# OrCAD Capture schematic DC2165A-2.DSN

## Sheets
1 PAGE4: size A
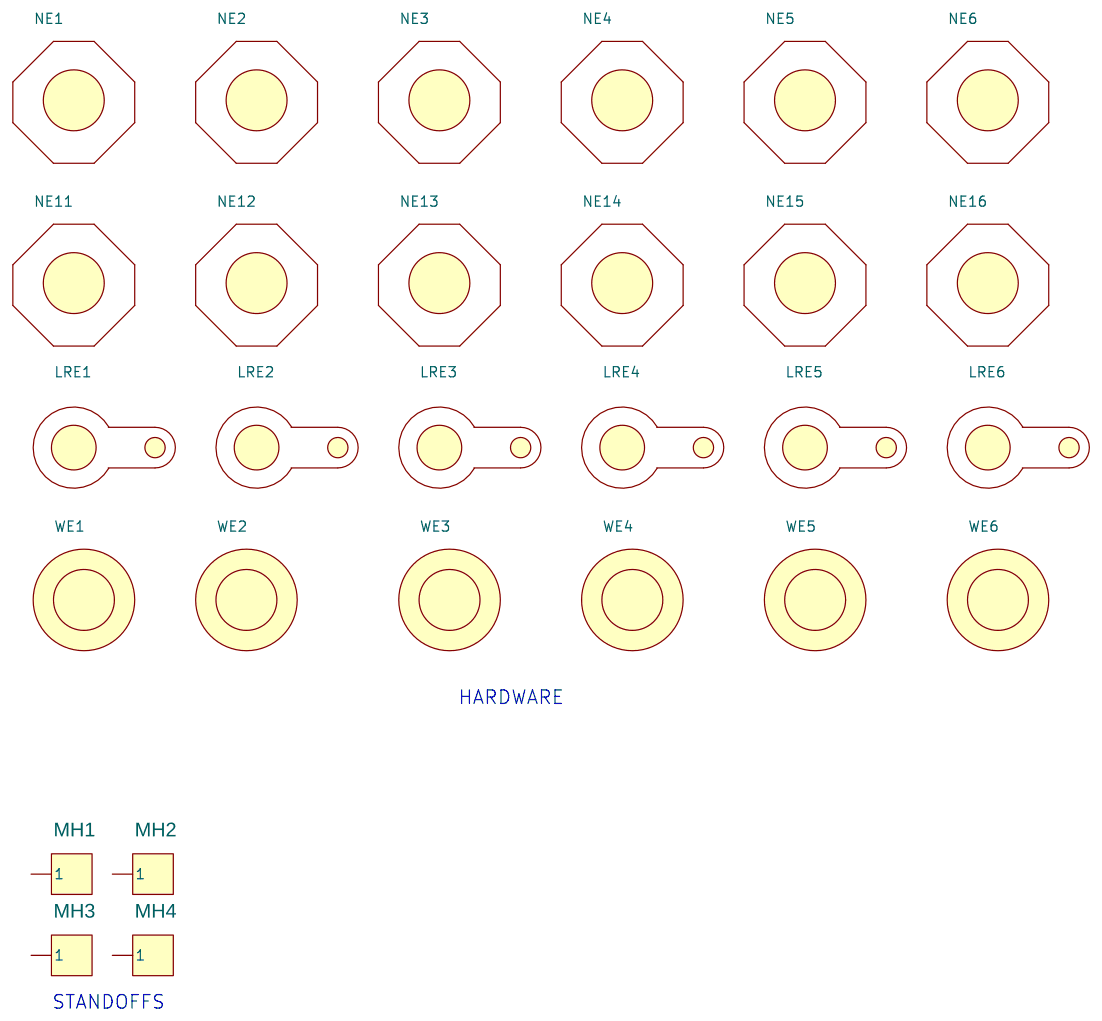
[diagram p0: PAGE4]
2 PAGE2: size Custom; title: HIGH EFFICIENCY, DUAL-OUTPUT SYNCHRONOUS BUCK; rev: 2; company: TM; note: CONVERTER WITH POWER SYSTEM MANAGEMENT
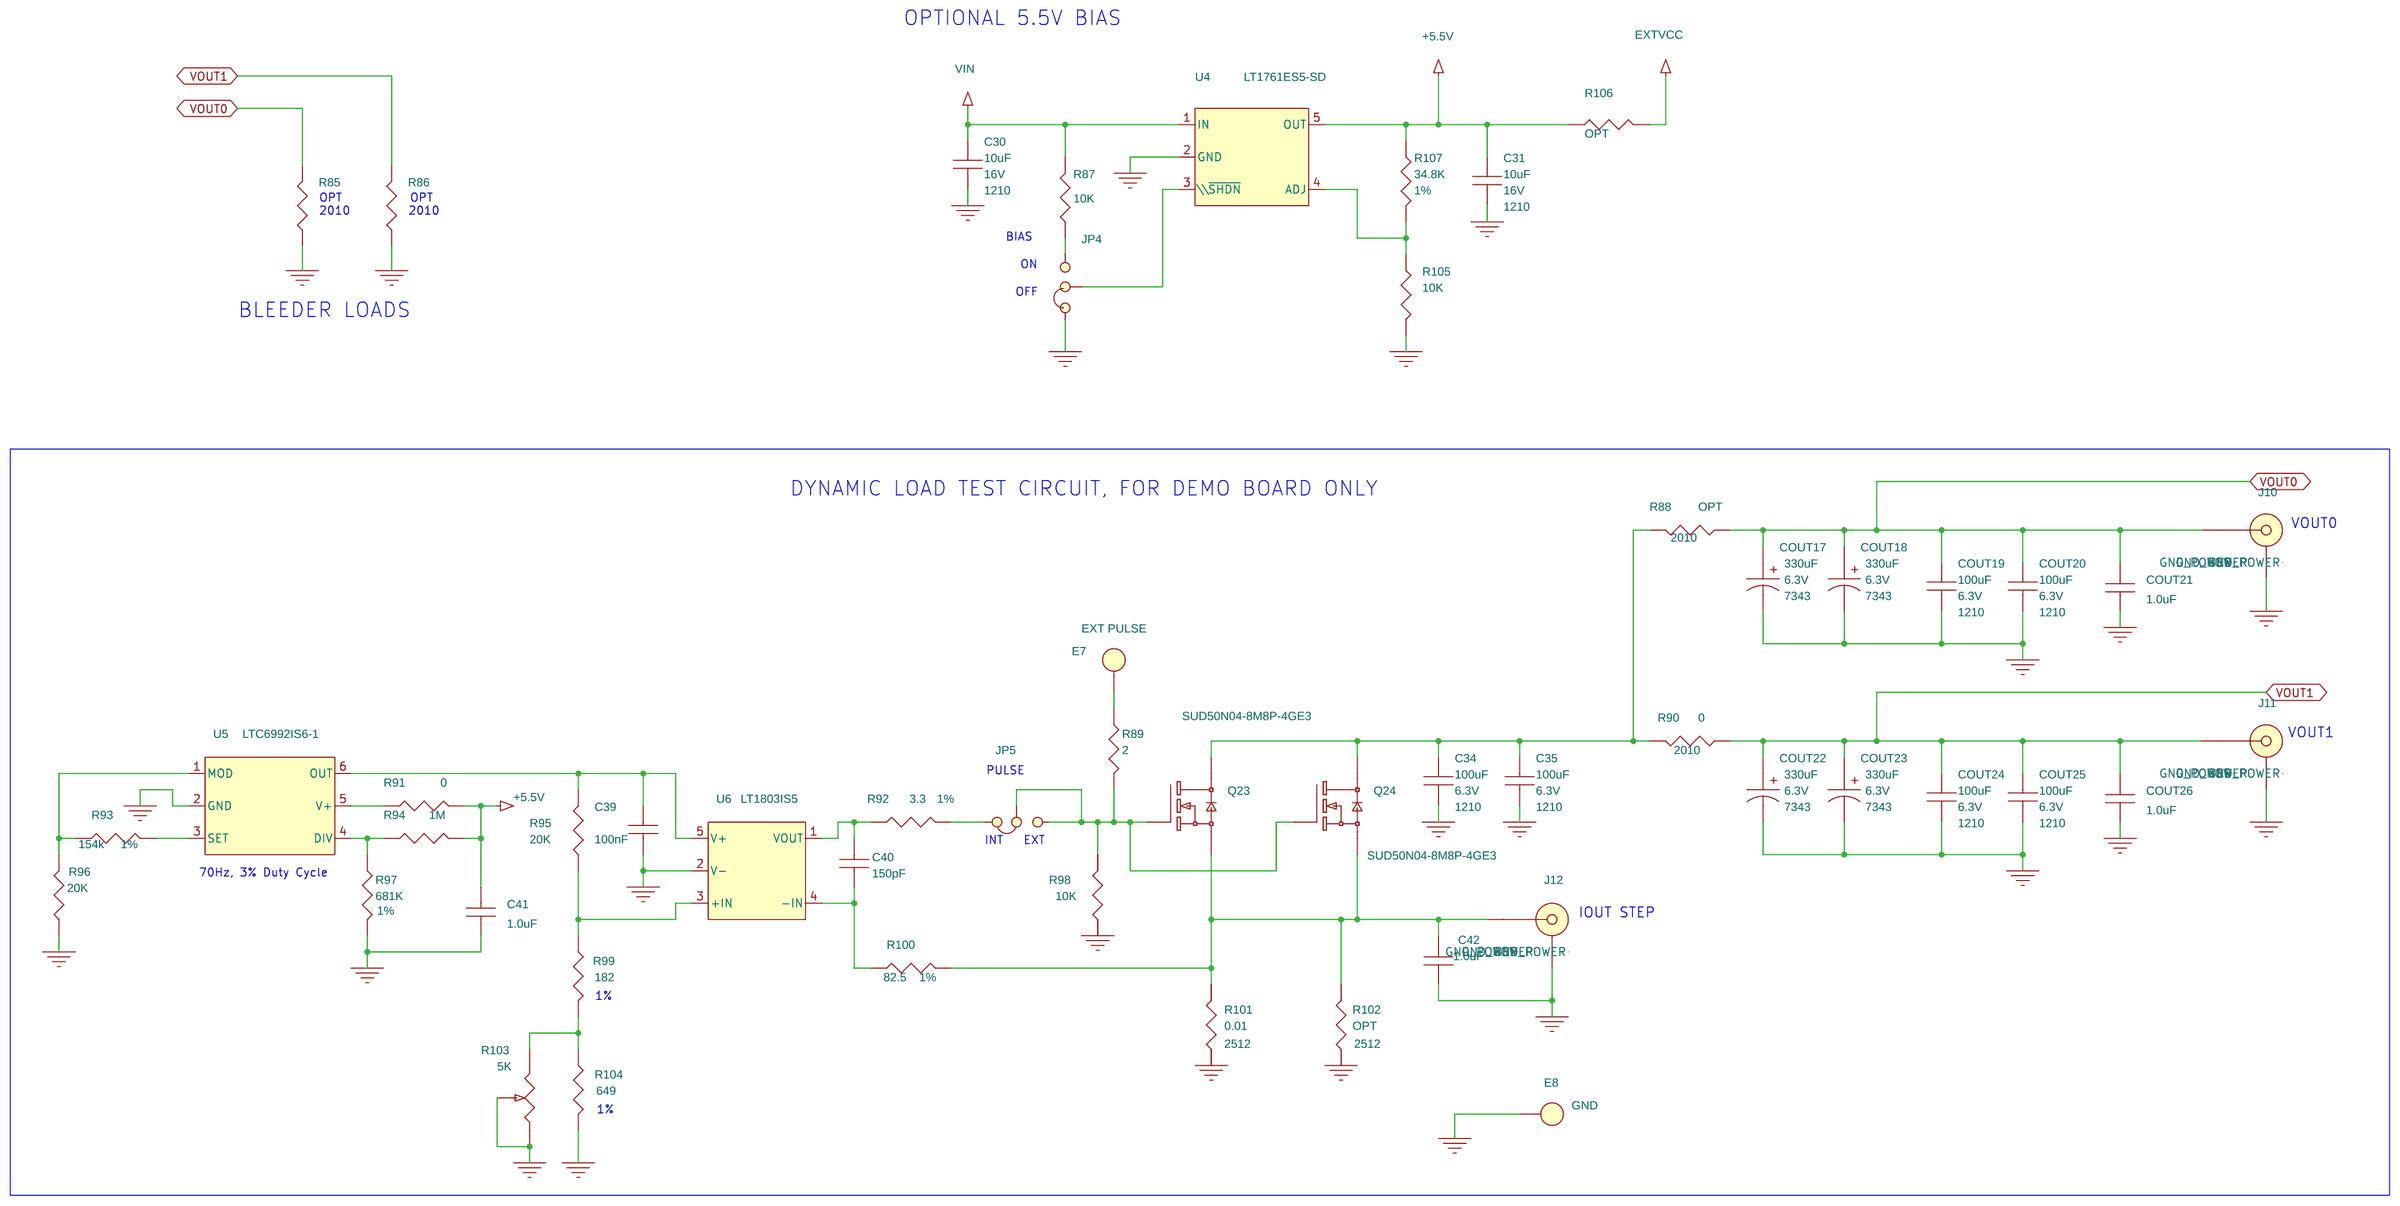
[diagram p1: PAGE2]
3 PAGE1: size Custom; title: HIGH EFFICIENCY, DUAL-OUTPUT SYNCHRONOUS BUCK; rev: 2; company: TM; note: CONVERTER WITH POWER SYSTEM MANAGEMENT
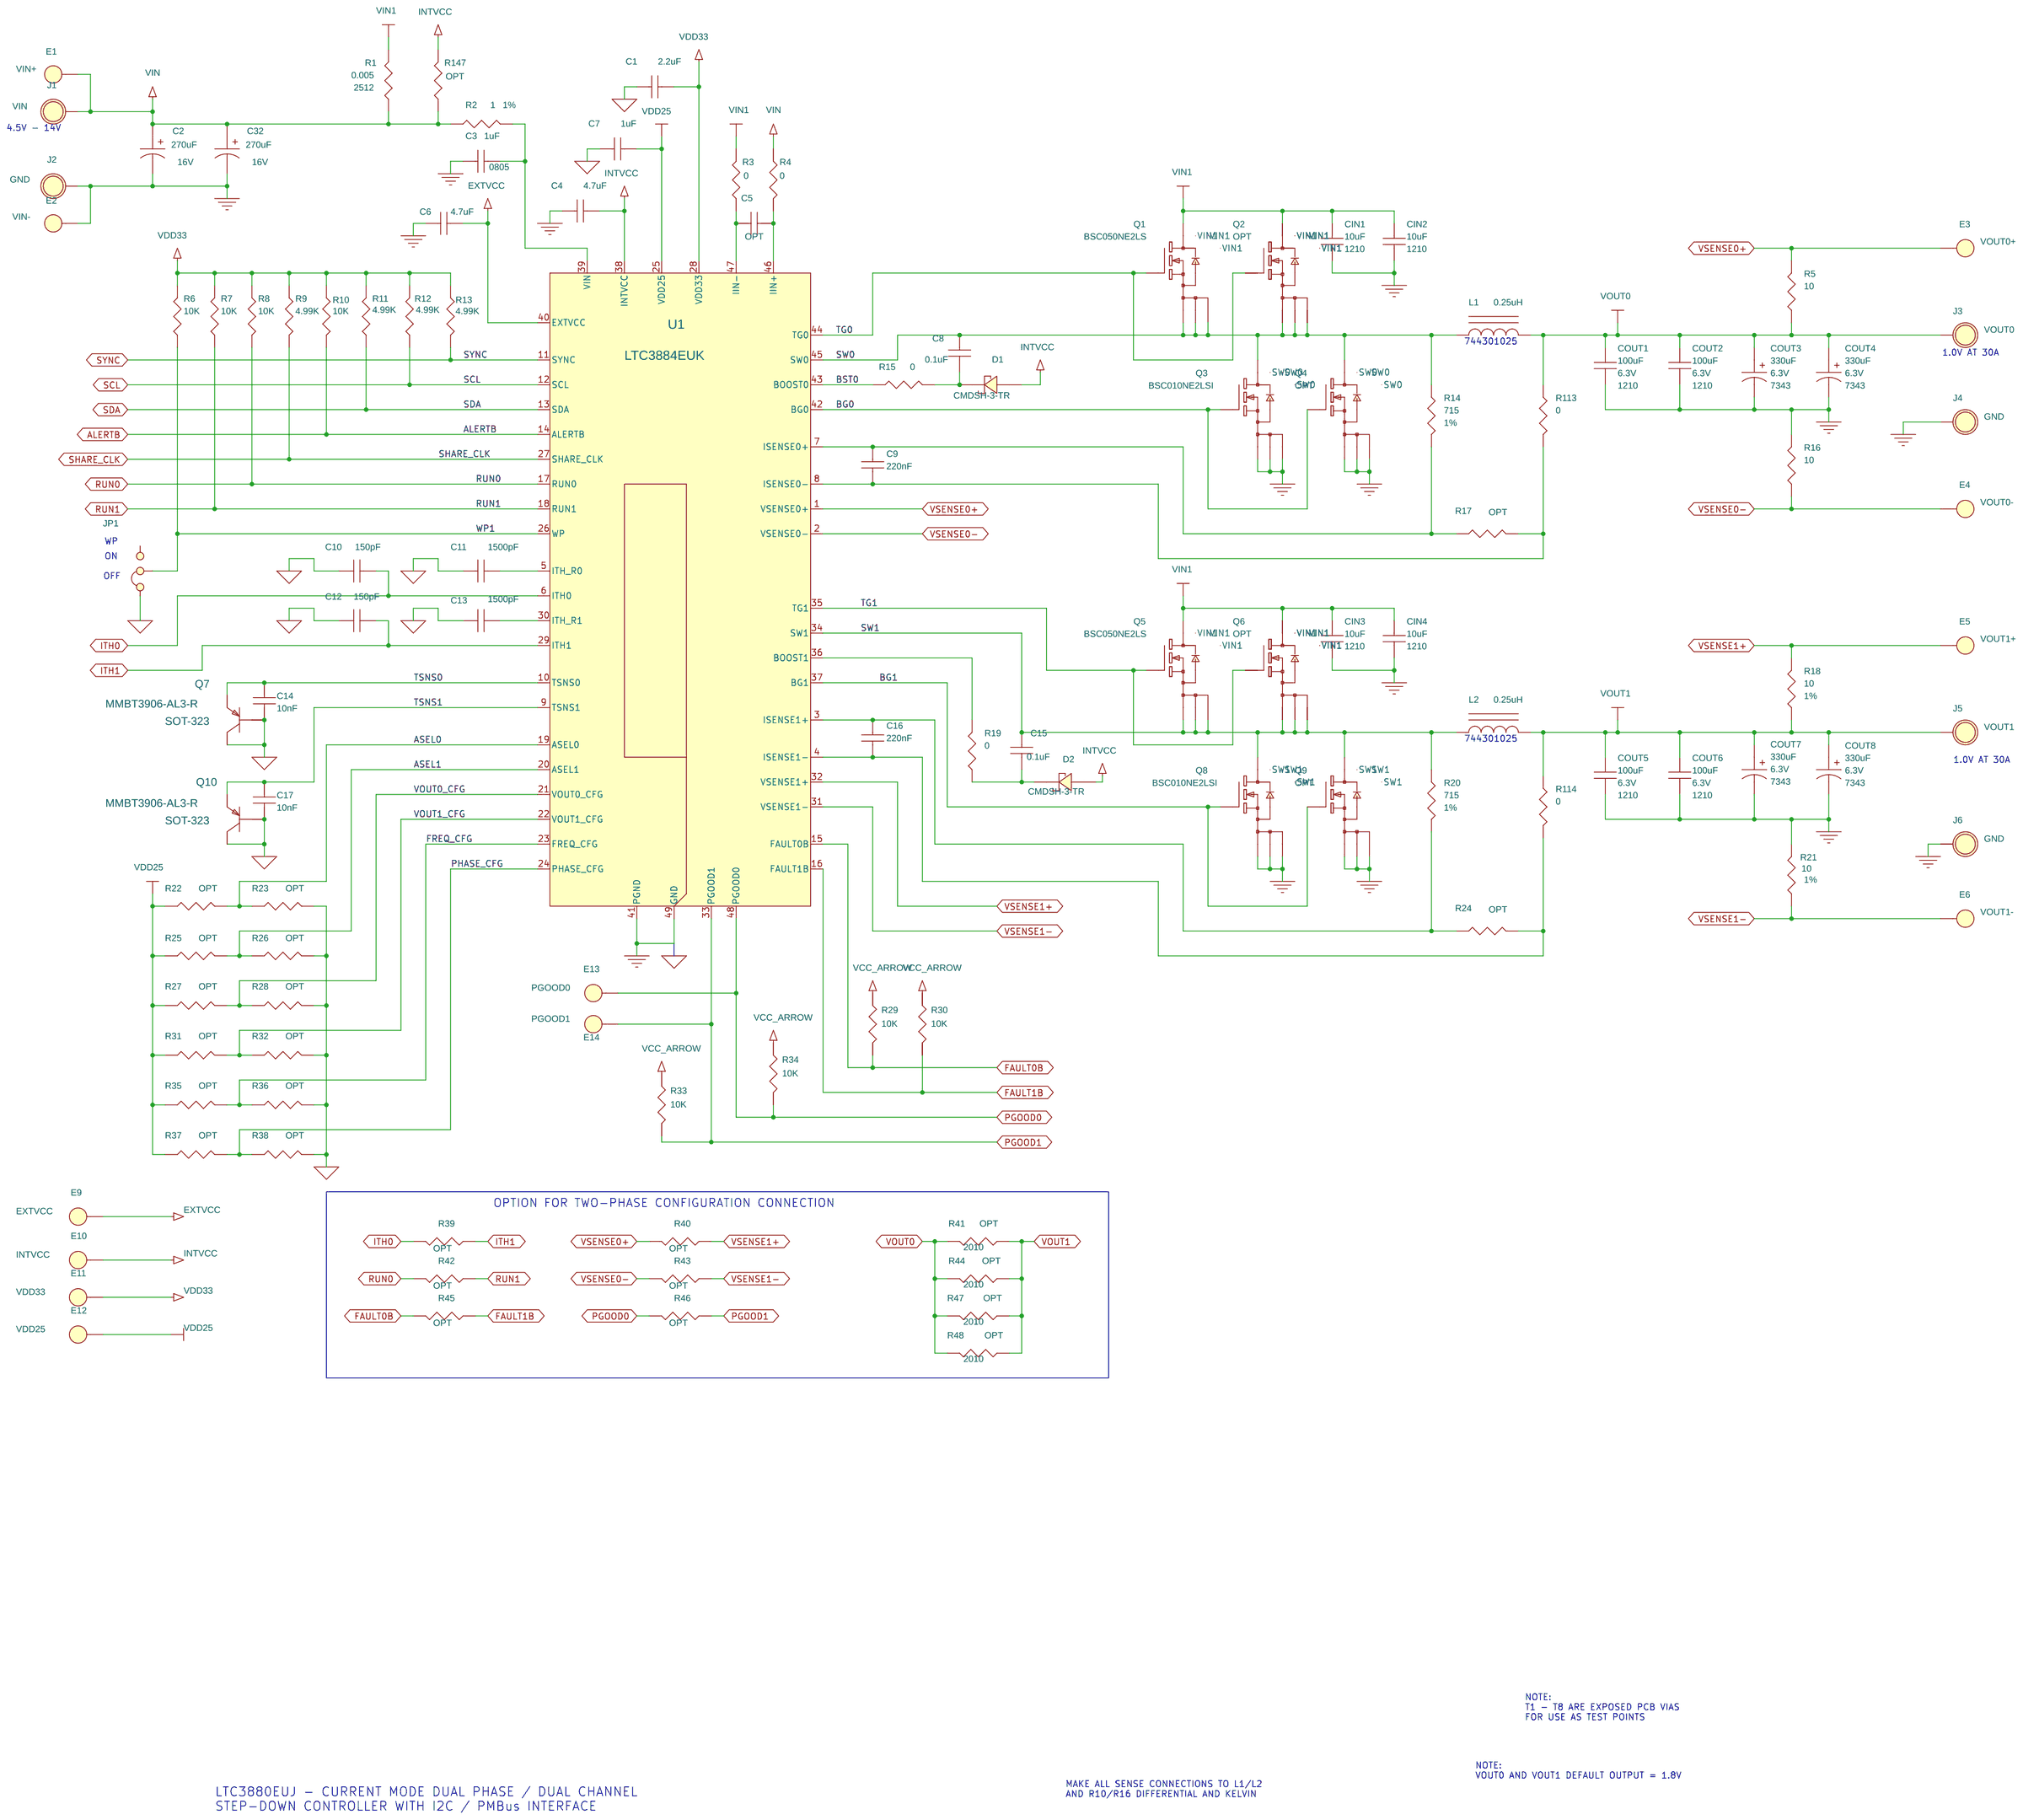
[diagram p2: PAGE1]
4 PAGE3: size Custom; title: HIGH EFFICIENCY, DUAL-OUTPUT SYNCHRONOUS BUCK; rev: 2; company: TM; note: CONVERTER WITH POWER SYSTEM MANAGEMENT
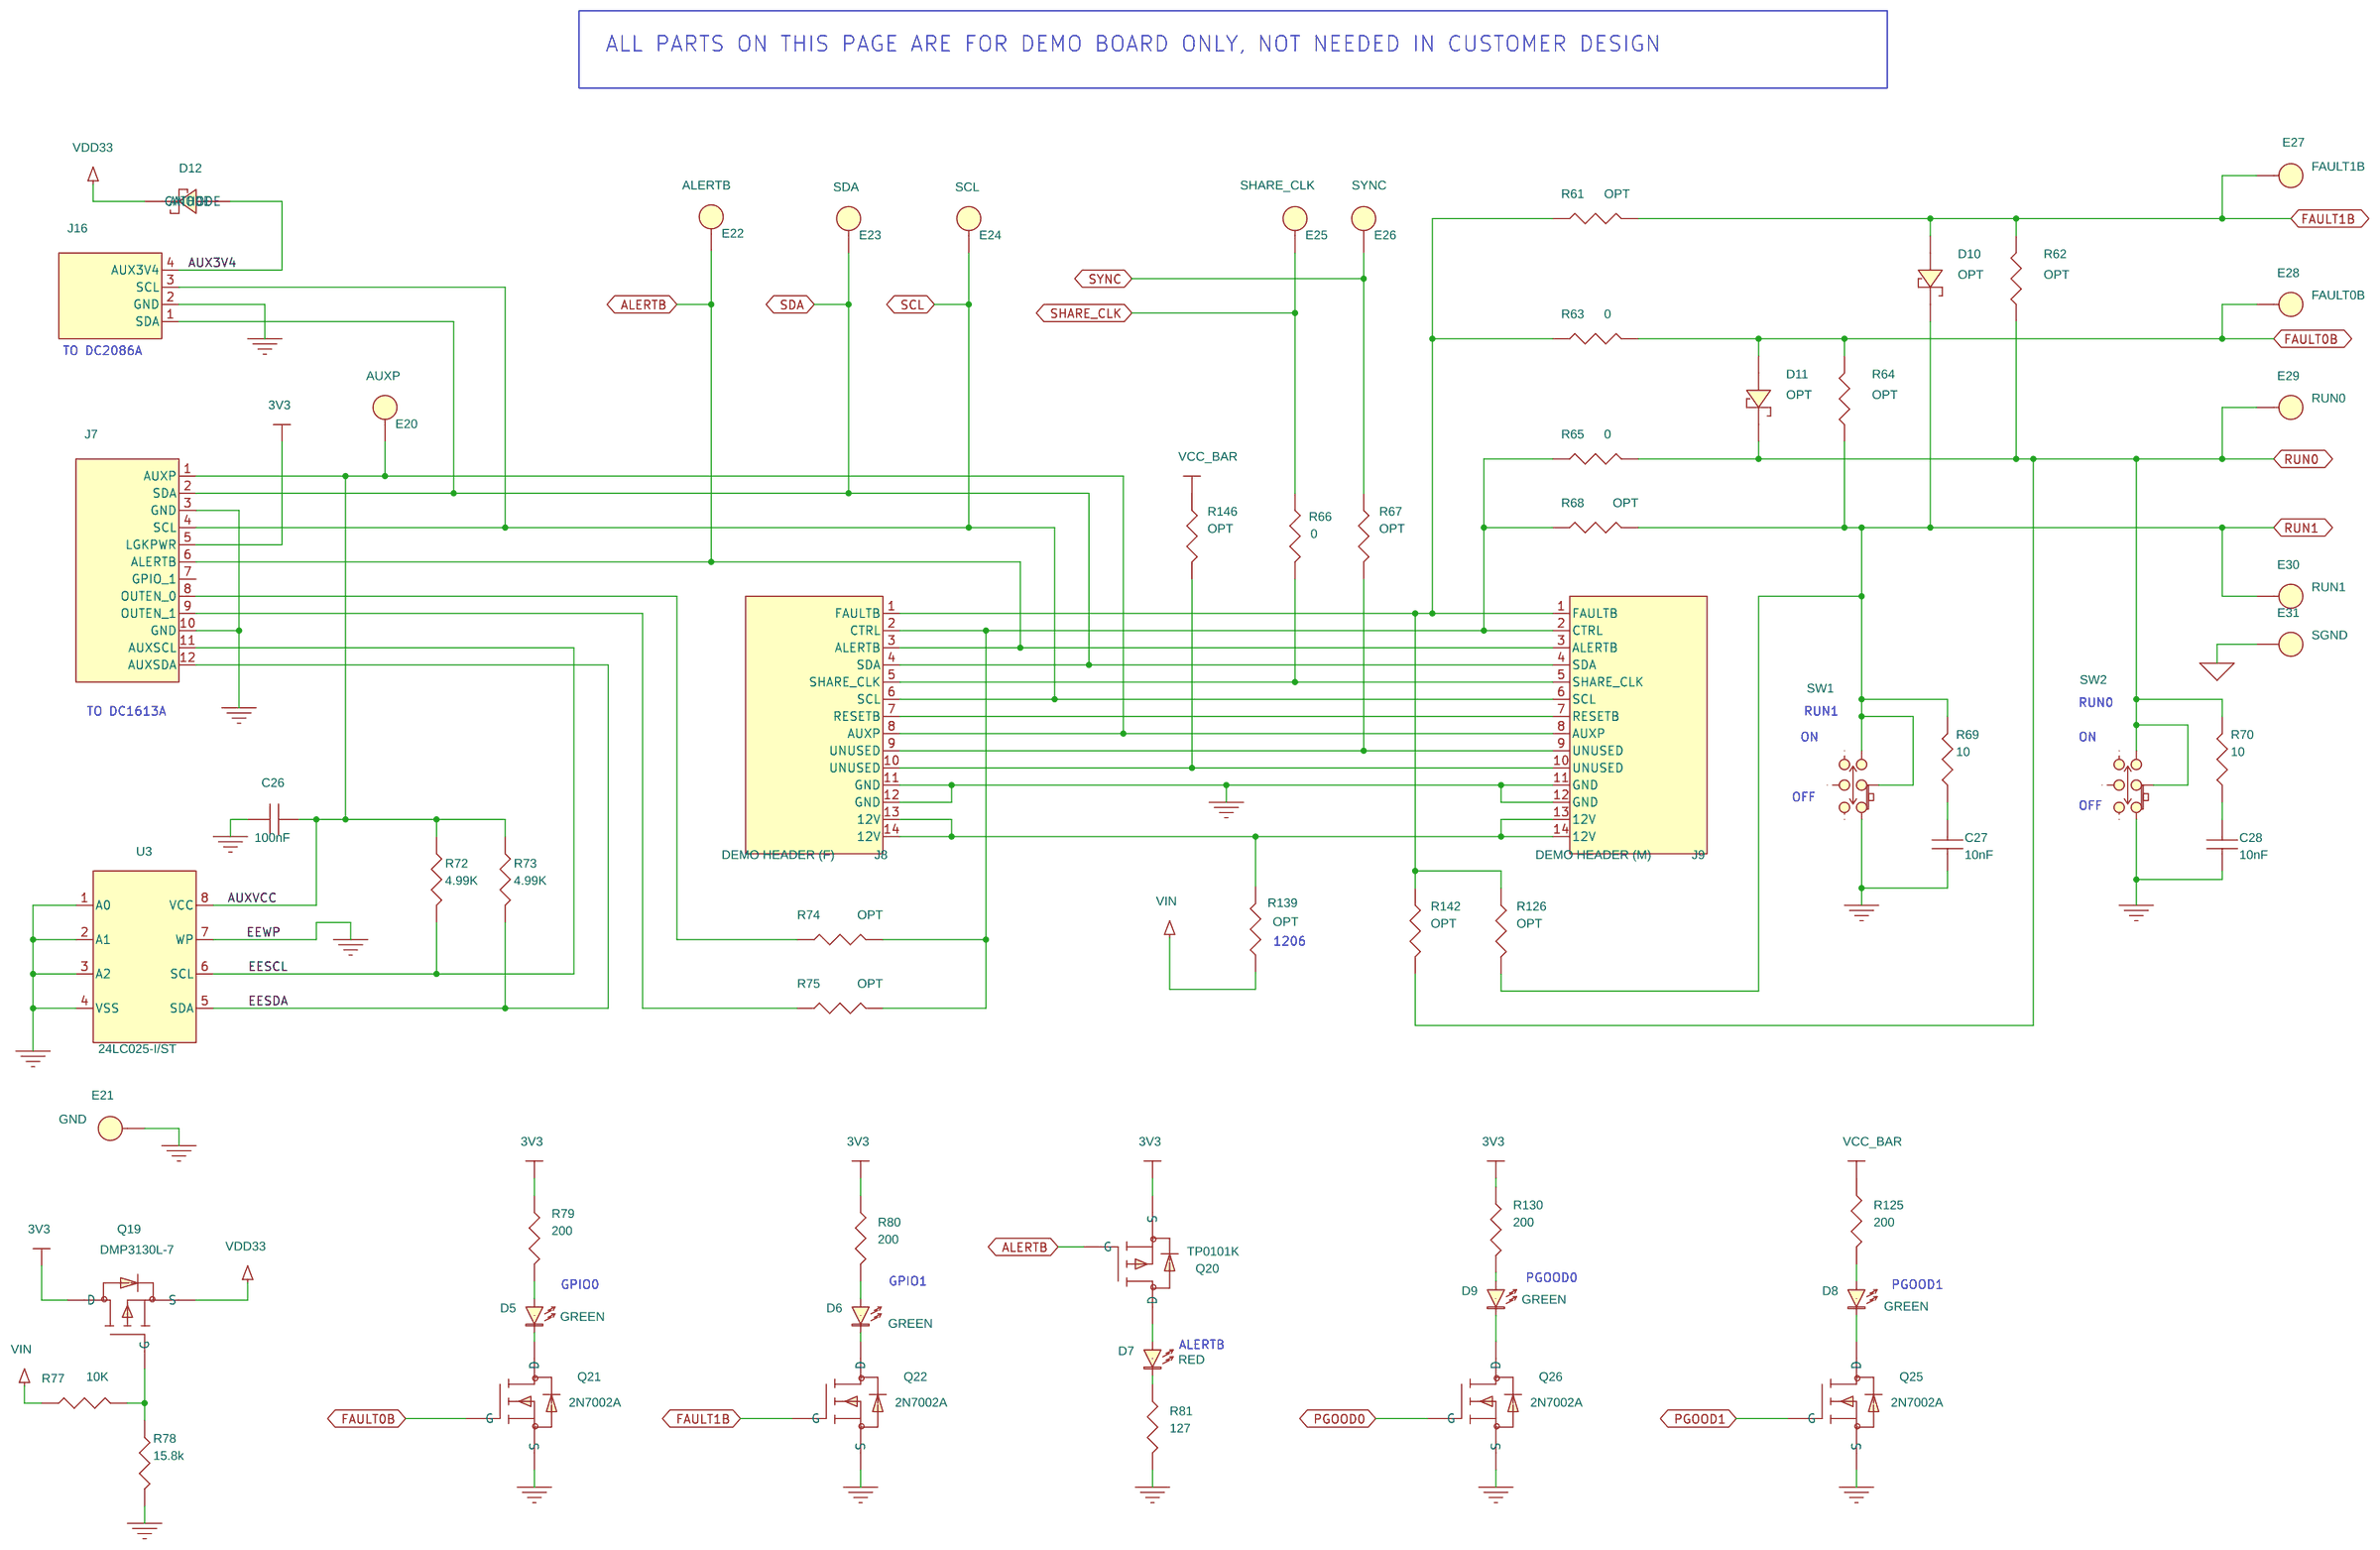
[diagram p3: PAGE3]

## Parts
sheet PAGE1
C1  2.2uF  [0603]
C2  270uF  [CAP\SAN\OSCON\SVF12]
C3  1uF  [0805]
C4  4.7uF  [0603]
C5  OPT  [0603]
C6  4.7uF  [0603]
C7  1uF  [0603]
C8  0.1uF  [0603]
C9  220nF  [0603]
C10  150pF  [0603]
C11  1500pF  [0603]
C12  150pF  [0603]
C13  1500pF  [0603]
C14  10nF  [0603]
C15  0.1uF  [0603]
C16  220nF  [0603]
C17  10nF  [0603]
C32  270uF  [CAP\SAN\OSCON\SVF12]
CIN1  10uF  [1210]
CIN2  10uF  [1210]
CIN3  10uF  [1210]
CIN4  10uF  [1210]
COUT1  100uF  [1210]
COUT2  100uF  [1210]
COUT3  330uF  [7343]
COUT4  330uF  [7343]
COUT5  100uF  [1210]
COUT6  100uF  [1210]
COUT7  330uF  [7343]
COUT8  330uF  [7343]
D1  CMDSH-3-TR  [SOD323]
D2  CMDSH-3-TR  [SOD323]
E1  VIN+  [TP\MMX\2501-2]
E2  VIN-  [TP\MMX\2501-2]
E3  VOUT0+  [TP\MMX\2501-2]
E4  VOUT0-  [TP\MMX\2501-2]
E5  VOUT1+  [TP\MMX\2501-2]
E6  VOUT1-  [TP\MMX\2501-2]
E9  EXTVCC  [TP\MMX\2501-2]
E10  INTVCC  [TP\MMX\2501-2]
E11  VDD33  [TP\MMX\2501-2]
E12  VDD25  [TP\MMX\2501-2]
E13  PGOOD0  [TP\MMX\2501-2]
E14  PGOOD1  [TP\MMX\2501-2]
J1  BANANA SMALL  [CON\LUG\10]
J2  BANANA SMALL  [CON\LUG\10]
J3  BANANA SMALL  [CON\LUG\10]
J4  BANANA SMALL  [CON\LUG\10]
J5  BANANA SMALL  [CON\LUG\10]
J6  BANANA SMALL  [CON\LUG\10]
JP1  JP3X1/079\NO\12  [SIP\3P\2MM]
L1  0.25uH  [IND\WURTH\7443010XX]
L2  0.25uH  [IND\WURTH\7443010XX]
Q1  BSC050NE2LS  [PWRPK_SO8]
Q2  OPT  [PWRPK_SO8]
Q3  BSC010NE2LSI  [PWRPK_SO8]
Q4  OPT  [PWRPK_SO8]
Q5  BSC050NE2LS  [PWRPK_SO8]
Q6  OPT  [PWRPK_SO8]
Q7  MMBT3906-AL3-R  [SOT-323]
Q8  BSC010NE2LSI  [PWRPK_SO8]
Q9  OPT  [PWRPK_SO8]
Q10  MMBT3906-AL3-R  [SOT-323]
R1  0.005  [2512]
R2  1  [0603]
R3  0  [0603]
R4  0  [0603]
R5  10  [0603]
R6  10K  [0603]
R7  10K  [0603]
R8  10K  [0603]
R9  4.99K  [0603]
R10  10K  [0603]
R11  4.99K  [0603]
R12  4.99K  [0603]
R13  4.99K  [0603]
R14  715  [0603]
R15  0  [0603]
R16  10  [0603]
R17  OPT  [0603]
R18  10  [0603]
R19  0  [0603]
R20  715  [0603]
R21  10  [0603]
R22  OPT  [0603]
R23  OPT  [0603]
R24  OPT  [0603]
R25  OPT  [0603]
R26  OPT  [0603]
R27  OPT  [0603]
R28  OPT  [0603]
R29  10K  [0603]
R30  10K  [0603]
R31  OPT  [0603]
R32  OPT  [0603]
R33  10K  [0603]
R34  10K  [0603]
R35  OPT  [0603]
R36  OPT  [0603]
R37  OPT  [0603]
R38  OPT  [0603]
R39  OPT  [0603]
R40  OPT  [0603]
R41  OPT  [2010]
R42  OPT  [0603]
R43  OPT  [0603]
R44  OPT  [2010]
R45  OPT  [0603]
R46  OPT  [0603]
R47  OPT  [2010]
R48  OPT  [2010]
R113  0  [0603]
R114  0  [0603]
R147  OPT  [0603]
U1  LTC3884EUK  [LT_UK48_7X7]
XJP1  SHUNT  [NONE]
sheet PAGE2
C30  10uF  [1210]
C31  10uF  [1210]
C34  100uF  [1210]
C35  100uF  [1210]
C39  100nF  [0603]
C40  150pF  [0603]
C41  1.0uF  [0603]
C42  1.0uF  [0603]
COUT17  330uF  [7343]
COUT18  330uF  [7343]
COUT19  100uF  [1210]
COUT20  100uF  [1210]
COUT21  1.0uF  [0603]
COUT22  330uF  [7343]
COUT23  330uF  [7343]
COUT24  100uF  [1210]
COUT25  100uF  [1210]
COUT26  1.0uF  [0603]
E7  EXT PULSE  [TP\MMX\2501-2]
E8  GND  [TP\MMX\2501-2]
J10  XXX  [BNC5]
J11  XXX  [BNC5]
J12  XXX  [BNC5]
JP4  JP3X1/079\NO\12  [SIP\3P\2MM]
JP5  JP3X1/079\NO\12  [SIP\3P\2MM]
Q23  SUD50N04-8M8P-4GE3  [TO-252]
Q24  SUD50N04-8M8P-4GE3  [TO-252]
R85  OPT  [2512]
R86  OPT  [2512]
R87  10K  [0603]
R88  OPT  [2010]
R89  2  [0603]
R90  0  [2010]
R91  0  [0603]
R92  3.3  [0603]
R93  154k  [0603]
R94  1M  [0603]
R95  20K  [0603]
R96  20K  [0603]
R97  681K  [0603]
R98  10K  [0603]
R99  182  [0603]
R100  82.5  [0603]
R101  0.01  [2512]
R102  OPT  [2512]
R103  5K  [BOURNS_3386P]
R104  649  [0603]
R105  10K  [0603]
R106  OPT  [0603]
R107  34.8K  [0603]
U4  LT1761ES5-SD  [LT_TSOT-23-S5]
U5  LTC6992IS6-1  [LT_S6]
U6  LT1803IS5  [LT_S5]
XJP4  SHUNT  [NONE]
XJP5  SHUNT  [NONE]
sheet PAGE3
C26  100nF  [0603]
C27  10nF  [0603]
C28  10nF  [0603]
D5  GREEN  [LED_0603]
D6  GREEN  [LED_0603]
D7  RED  [LED_0603]
D8  GREEN  [LED_0603]
D9  GREEN  [LED_0603]
D10  OPT  [SOD323]
D11  OPT  [SOD323]
D12  DIODE SCHOTTKY  [SOD882]
E20  AUXP  [TP\MMX\2501-2]
E21  GND  [TP\MMX\2501-2]
E22  ALERTB  [TP\MMX\2501-2]
E23  SDA  [TP\MMX\2501-2]
E24  SCL  [TP\MMX\2501-2]
E25  SHARE_CLK  [TP\MMX\2501-2]
E26  SYNC  [TP\MMX\2501-2]
E27  FAULT1B  [TP\MMX\2501-2]
E28  FAULT0B  [TP\MMX\2501-2]
E29  RUN0  [TP\MMX\2501-2]
E30  RUN1  [TP\MMX\2501-2]
E31  SGND  [TP\MMX\2501-2]
J7  HD2X6-079  [HD2X6-079-MOLEX]
J8  DEMO HEADER (F)  [NPPN072FJFN-RC]
J9  DEMO HEADER (M)  [NPPN072FJFN]
J16  HD2X6-079-PMBUS_0  [CON\HRS\DF3A-4P-2DSA]
Q19  DMP3130L-7  [SOT23]
Q20  TP0101K  [SOT23]
Q21  2N7002A  [SOT23]
Q22  2N7002A  [SOT23]
Q25  2N7002A  [SOT23]
Q26  2N7002A  [SOT23]
R61  OPT  [0603]
R62  OPT  [0603]
R63  0  [0603]
R64  OPT  [0603]
R65  0  [0603]
R66  0  [0603]
R67  OPT  [0603]
R68  OPT  [0603]
R69  10  [0603]
R70  10  [0603]
R72  4.99K  [0603]
R73  4.99K  [0603]
R74  OPT  [0603]
R75  OPT  [0603]
R77  10K  [0603]
R78  15.8k  [0603]
R79  200  [0603]
R80  200  [0603]
R81  127  [0603]
R125  200  [0603]
R126  OPT  [0603]
R130  200  [0603]
R139  OPT  [1206]
R142  OPT  [0603]
R146  OPT  [0603]
SW1  JP3X1/079\NO\12  [JS202011]
SW2  JP3X1/079\NO\12  [JS202011]
U3  24LC025-I/ST  [TSSOP-8_4.4MM]
sheet PAGE4
LRE1  Lug_Ring
LRE2  Lug_Ring
LRE3  Lug_Ring
LRE4  Lug_Ring
LRE5  Lug_Ring
LRE6  Lug_Ring
MH1  CON1  [KEYSTONE_8831]
MH2  CON1  [KEYSTONE_8831]
MH3  CON1  [KEYSTONE_8831]
MH4  CON1  [KEYSTONE_8831]
NE1  NUT
NE2  NUT
NE3  NUT
NE4  NUT
NE5  NUT
NE6  NUT
NE11  NUT
NE12  NUT
NE13  NUT
NE14  NUT
NE15  NUT
NE16  NUT
WE1  Washer
WE2  Washer
WE3  Washer
WE4  Washer
WE5  Washer
WE6  Washer

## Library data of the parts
C1 = CAP_NP: CAP, 0603 2.2uF 20% 6.3V X5R; Part Number: AVX 06036D225MAT2A; Volts/Amps/Watts: 50V
C2 C32 = CAPR12X5_0: CAP, 270uF 20% 16V OSCON; Component: cap; Manufacturer: SANYO; Part Number: PANASONIC 16SVPC270M; Tolerance: 20%; Type: OS-CON; Volts/Amps/Watts: 16V
C3 = CAP_NP_0: CAP, 0805 1uF 10% 16V X7R; Part Number: AVX 0805YC105KAT2A
C4 = CAP_NP: CAP, 0603 4.7uF 10% 10V X5R; Part Number: AVX 0603ZD475KAT2A
C5 = CAP_NP: CAP, 0603 OPTION; Part Number: OPTION
C6 = CAP_NP: CAP, 0603 4.7uF 20% 25V X5R; Part Number: TDK  C1608X5R1E475M080AC
C7 C41 COUT21 COUT26 = CAP_NP: CAP, 0603 1uF 20% 25V X5R; Part Number: AVX 06033D105MAT2A
C8 C15 = CAP_NP_0: CAP, 0603 0.1uF 10% 25V X7R; Part Number: AVX 06033C104KAT2A; VOLTAGE: 50V
C9 C16 = CAP_NP: CAP, 0603 220nF 10% 25V X7R; Part Number: TDK C1608X7R1E224K
C10 C12 C40 = CAP_NP: CAP, 0603 150pF 5% 50V NPO; Part Number: AVX 06035A151JAT2A
C11 C13 = CAP_NP: CAP, 0603 1500pF 5% 50V C0G; Part Number: MURATA GRM1885C1H152JA01D
C14 C17 C27 C28 = CAP_NP: CAP, 0603 10nF 10% 25V X7R; Part Number: AVX 06033C103KAT2A
CIN1-CIN4 = CAP_NP_0: CAP, 1210 10uF 20% 35V X5R; Part Number: AVX 1210DD106MAT2A; VOLTAGE: 50V; Volts/Amps/Watts: 6.3V
C34 C35 COUT1 COUT2 COUT5 COUT6 COUT19 COUT20 COUT24 COUT25 = CAP_NP_0: CAP, 1210 100uF 20% 6.3V X5R; Part Number: AVX 12106D107MAT2A; VOLTAGE: 50V; Volts/Amps/Watts: 6.3V
COUT3 COUT4 COUT7 COUT8 COUT17 COUT18 COUT22 COUT23 = t510x337k010as: CAP, 7343 330uF 20% 6.3V POSCAP; 1st Part Field: 6.3V; 3rd Part Field: POSCAP; Part Number: PANASONIC 6TPF330M9L
D1 D2 = DIODE_SCHOTTKY_9: DIODE, SCHOTTKY 30V, 100mA; Part Number: CENTRAL SEMI CMDSH-3-TR
E1-E14 E20-E31 = E_0: TURRET; Part Number: MILL MAX 2501-2-00-80-00-00-07-0
J1 = BANANA_SMALL_0: STUD, TEST PIN; Component: conn; Label: VIN; Part Number: PEM KFH-032-10
J2 J4 J6 = BANANA_SMALL_0: STUD, TEST PIN; Component: conn; Label: GND; Part Number: PEM KFH-032-10
J3 = BANANA_SMALL_0: STUD, TEST PIN; Component: conn; Label: VOUT0; Part Number: PEM KFH-032-10
J5 = BANANA_SMALL_0: STUD, TEST PIN; Component: conn; Label: VOUT1; Part Number: PEM KFH-032-10
JP1 JP4 JP5 = JP3X1_079_NO_12_1: HEADER, SINGLE ROW 3PIN; Part Number: WURTH ELEKTRONIK, 62000311121
L1 L2 = INDUCTOR_IRON: IND, 0.25uH; Part Number: WURTH ELEKTRONIK 744301025
Q1 Q5 = 2N7002_0: XSTR, POWER MOSFET; Part Number: INFINEON BSC050NE2LS
Q2 Q6 = 2N7002_0: XSTR, POWER MOSFET OPTION; Part Number: OPTION
Q3 = 2N7002_1: XSTR, POWER MOSFET; Part Number: INFINEON BSC010NE2LSI
Q4 = 2N7002_2: XSTR, POWER MOSFET OPTION; Part Number: OPTION
Q7 Q10 = MMBT3906_SOT_0: XSTR, PNP GENERAL PURPOSE; Part Number: DIODES INC. MMST3906-7-F
Q8 = 2N7002_3: XSTR, POWER MOSFET; Part Number: INFINEON BSC010NE2LSI
Q9 = 2N7002_4: XSTR, POWER MOSFET OPTION; Part Number: OPTION
R1 = RES0603_0: RES, 2512 0.005 OHMS 1% 1W; Label: 2; Manufacturer: Rohm; Manufacturer P/N: RHM0.0GCT-ND; Part Number: SUSUMU KRL3264E-C-R005-F-T5; Vendor: Digikey; Vendor P/N: RHM0.0GCT-ND; Volts/Amps/Watts: 0.1W
R2 = RES0603_0: RES, 0603 1 OHMS 1% 1/10W; Component: res; Label: <label>; Manufacturer: Panasonic; Manufacturer P/N: ERJ-3EKF5901V; Part Number: VISHAY CRCW06031R00FNEA; Tolerance: 1%; Vendor: Digikey; Vendor P/N: P5.90KHCT-ND; Volts/Amps/Watts: 0.1W
R3 R66 = RES0603_0: RES, 0603 0 OHMS JUMPER; Manufacturer: Rohm; Manufacturer P/N: RHM0.0GCT-ND; Part Number: VISHAY CRCW06030000Z0EA; Tolerance: 5%; Vendor: Digikey; Vendor P/N: RHM0.0GCT-ND; Volts/Amps/Watts: 0.1W
R4 = RES0603_0: RES, 0603 0 OHMS JUMPER; Manufacturer: ROHM; Manufacturer P/N: MCR03EZPFX1002; Part Number: VISHAY CRCW06030000Z0EA; Vendor: Digikey; Vendor P/N: RHM10.0KHCT-ND; Volts/Amps/Watts: 0.1W
R5 R16 R18 = RES0603_0: RES, 0603 10 OHMS 1% 1/10W; Manufacturer: Yageo; Manufacturer P/N: RC0603JR-070RL; Part Number: VISHAY CRCW060310R0FKEA; Tolerance: 1%; Vendor: Digikey; Vendor P/N: 311-0.0GRCT-ND; Volts/Amps/Watts: 0.1W
R6 R7 R29 R30 R33 R34 = RES0603_0: RES, 0603 10K OHMS 5% 1/10W; Manufacturer: Panasonic; Manufacturer P/N: ERJ-3EKF2002V; Part Number: VISHAY CRCW060310K0JNEA; Vendor: Digikey; Vendor P/N: P20.0KHCT-ND; Volts/Amps/Watts: 0.1W
R8 R10 = RES0603_0: RES, 0603 10K OHMS 5% 1/10W; Manufacturer: ROHM; Manufacturer P/N: MCR03EZPFX1002; Part Number: VISHAY CRCW060310K0JNEA; Vendor: Digikey; Vendor P/N: RHM10.0KHCT-ND; Volts/Amps/Watts: 0.1W
R9 R11-R13 = RES0603_0: RES, 0603 4.99K OHMS 1% 1/10W; Manufacturer: ROHM; Manufacturer P/N: MCR03EZPFX4991; Part Number: VISHAY CRCW06034K99FKEA; Vendor: Digikey; Vendor P/N: RHM10.0KHCT-ND; Volts/Amps/Watts: 0.1W
R14 = R_1: RES, 0603 715 OHMS 1% 1/10W; %: 0.1%; Part Number: VISHAY CRCW0603715RFKEA; Tol: 1%
R15 R19 R91 = RES0603_0: RES, 0603 0 OHMS JUMPER; Component: res; Label: <label>; Manufacturer: Panasonic; Manufacturer P/N: ERJ-3EKF5901V; Part Number: VISHAY CRCW06030000Z0EA; Tolerance: 1%; Vendor: Digikey; Vendor P/N: P5.90KHCT-ND; Volts/Amps/Watts: 0.1W
R17 R24 = R_1: RES, 0603 OPTION; %: 0.1%; Part Number: OPTION
R20 = R_1: RES, 0603 715 OHMS 1% 1/10W; %: 1%; Part Number: VISHAY CRCW0603715RFKEA; Tol: 1%
R21 = RES0603_0: RES, 0603 10 OHMS 1% 1/10W; Manufacturer: Rohm; Manufacturer P/N: MCR03EZPFX1000; Part Number: VISHAY CRCW060310R0FKEA; Tolerance: 1%; Vendor: Digikey; Vendor P/N: RHM100HCT-ND; Volts/Amps/Watts: 1W
R22 R28 R32 R36 R38-R40 R42 R43 R45 R46 = RES0603_0: RES, 0603 OPTION; Manufacturer: Panasonic; Manufacturer P/N: ERJ-3EKF2002V; Part Number: OPTION; Vendor: Digikey; Vendor P/N: P20.0KHCT-ND; Volts/Amps/Watts: 0.1W
R23 R147 = RES0603_0: RES, 0603 OPTION; Manufacturer: Rohm; Manufacturer P/N: RHM0.0GCT-ND; Part Number: OPTION; Tolerance: 5%; Vendor: Digikey; Vendor P/N: RHM0.0GCT-ND; Volts/Amps/Watts: 0.1W
R25 = RES0603_0: RES, 0603 OPTION; Manufacturer: Panasonic; Manufacturer P/N: ERJ-3EKF5901V; Part Number: OPTION; Vendor: Digikey; Vendor P/N: P5.90KHCT-ND; Volts/Amps/Watts: 0.1W
R26 = RES0603_0: RES, 0603 OPTION; Manufacturer: Panasonic; Manufacturer P/N: ERJ-3EKF2002V; Part Number: OPTION; Tolerance: 5%; Vendor: Digikey; Vendor P/N: P20.0KHCT-ND; Volts/Amps/Watts: 0.1W
R27 = RES0603_0: RES, 0603 OPTION; Manufacturer: Panasonic; Manufacturer P/N: ERJ-3EKF1000V; Part Number: OPTION; Vendor: Digikey; Vendor P/N: P100HCT-ND; Volts/Amps/Watts: 0.1W
R31 = RES0603_0: RES, 0603 OPTION; Manufacturer: Panasonic; Manufacturer P/N: ERJ-3EKF1021V; Part Number: OPTION; Vendor: Digikey; Vendor P/N: P1.02KHCT-ND; Volts/Amps/Watts: 0.1W
R35 R37 = RES0603_0: RES, 0603 OPTION; Manufacturer: ROHM; Manufacturer P/N: MCR03EZPFX1002; Part Number: OPTION; Vendor: Digikey; Vendor P/N: RHM10.0KHCT-ND; Volts/Amps/Watts: 0.1W
R41 R44 R47 R48 R88 = RES0603_0: RES, 2010 OPTION; Label: 2; Manufacturer: Rohm; Manufacturer P/N: RHM0.0GCT-ND; Part Number: OPTION; Vendor: Digikey; Vendor P/N: RHM0.0GCT-ND; Volts/Amps/Watts: 0.1W
R113 R114 = R_1: RES, 0603 0 OHMS JUMPER; %: 0.1%; Part Number: VISHAY CRCW06030000Z0EA; Tol: 1%
U1 = LTC3884EUK: IC, LTC3884; Component: IC; Manufacturer: LTC; Manufacturer P/N: LTC3880_M0001; Part Number: LINEAR TECH. LTC3884EUK#10E1-1PBF-ES
XJP1 XJP4 XJP5 = SHUNT: Part Number: WURTH ELEKTRONIK, 60800213421
C30 C31 = CAP_NP_1: CAP, 1210 10uF 10% 16V X7R; Part Number: MURATA GRM32DR71C106KA01; Voltage: 16V
C26 C39 = CAP_NP: CAP, 0603 100nF 20% 16V X7R; Part Number: AVX 0603YC104MAT2A
C42 = CAP_NP_1: CAP, 0603 1uF 20% 25V X5R; Part Number: AVX 06033D105MAT2A
J10 = BNC5-SCH_14: CONN, BNC, 5 PINS; Part Number: CONNEX 112404
J11 = BNC5-SCH_15: CONN, BNC, 5 PINS; Part Number: CONNEX 112404; Pin Numbers Visible: <Pin Numbers Visible>
J12 = BNC5-SCH_16: CONN, BNC, 5 PINS; Part Number: CONNEX 112404
Q23 Q24 = 2N7002_13: XSTR, MOSFET, N-CHANNEL 30V; Part Number: VISHAY SUD50N04-8M8P-4GE3
R85 = RES0603_5: RES, 2010 OPTION; Label: 1W; Manufacturer: VISHAY; Manufacturer P/N: CRCW251230R0JNEG; Part Number: OPTION; Tolerance: 5%
R86 = RES0603_6: RES, 2010 OPTION; Label: 1W; Part Number: OPTION; Tolerance: 5%
R87 = RESISTOR_1: RES, 0603 10K OHMS 5% 1/10W; Part Number: VISHAY CRCW060310K0JNEA
R89 = RES0603_0: RES, 0603 2 OHMS 5% 1/10W; Manufacturer: ROHM; Manufacturer P/N: MCR03EZPFX4991; Part Number: VISHAY CRCW06032R00JNEA; Vendor: Digikey; Vendor P/N: RHM4.99KHCT-ND; Volts/Amps/Watts: 0.1w
R90 = RES0603_0: RES, 2010 0 OHM JUMPER; Label: OPT 0; Manufacturer: Rohm; Manufacturer P/N: RHM0.0GCT-ND; Part Number: VISHAY CRCW20100000Z0EA; Tolerance: 5%; Vendor: Digikey; Vendor P/N: RHM0.0GCT-ND; Volts/Amps/Watts: 0.1W
R92 = RES0603_0: RES, 0603 3.3 OHMS 1% 1/10W; Manufacturer: ROHM; Manufacturer P/N: MCR03EZPFX4991; Part Number: VISHAY CRCW06033R30FKEA; Tolerance: 1%; Vendor: Digikey
R93 = RES0603_0: RES, 0603 154K OHMS 1% 1/10W; Component: res; Label: <label>; Manufacturer: Panasonic; Manufacturer P/N: ERJ-3EKF5901V; Part Number: VISHAY CRCW0603154KFKEA; Tolerance: 1%; Vendor: Digikey; Vendor P/N: P5.90KHCT-ND; Volts/Amps/Watts: 0.1W
R94 = RES0603_0: RES, 0603 1M OHMS 5% 1/10W; Label: OPT 0; Manufacturer: Rohm; Manufacturer P/N: RHM0.0GCT-ND; Part Number: VISHAY CRCW06031M00JNEA; Vendor: Digikey
R95 R96 = RES0603_0: RES, 0603 20K OHMS 5% 1/10W; Manufacturer: Panasonic; Manufacturer P/N: ERJ-3EKF2002V; Part Number: VISHAY CRCW060320K0JNEA; Vendor: Digikey; Vendor P/N: P20.0KHCT-ND; Volts/Amps/Watts: 0.1W
R97 = RES0603_0: RES, 0603 681K OHMS 1% 1/10W; Manufacturer: ROHM; Manufacturer P/N: MCR03EZPFX4991; Part Number: VISHAY CRCW0603681KFKEA; Tolerance: 1%
R98 = RES0603_0: RES, 0603 10K OHMS 5% 1/10W; Manufacturer: Panasonic; Manufacturer P/N: ERJ-3EKF2002V; Part Number: VISHAY CRCW060310K0JNEA; Vendor: Digikey
R99 = RES0603_0: RES, 0603 182 OHMS 1% 1/10W; Manufacturer: ROHM; Manufacturer P/N: MCR03EZPFX4991; Part Number: VISHAY CRCW0603182RFKEA; Vendor: Digikey; Vendor P/N: RHM4.99KHCT-ND; Volts/Amps/Watts: 0.1w
R100 = RES0603_0: RES, 0603 82.5 OHMS 1% 1/10W; Manufacturer: ROHM; Manufacturer P/N: MCR03EZPFX4991; Part Number: VISHAY CRCW060382R5FKEA; Tolerance: 1%; Vendor: Digikey
R101 = RES0603_5: RES, 2512 0.01 OHMS 1% 1W; Label: 1W; Manufacturer: VISHAY; Manufacturer P/N: CRCW251230R0JNEG; Part Number: VISHAY WSL2512R0100FEA; Tolerance: 5%
R102 = RES0603_5: RES, 2512 OPTION; Label: 1W; Manufacturer: VISHAY; Manufacturer P/N: CRCW251230R0JNEG; Part Number: OPTION; Tolerance: 5%
R103 = POT: RES, VARIABLE 5K; Part Number: BOURNS 3386P-1-502-LF
R104 = RES0603_0: RES, 0603 649 OHMS 1% 1/10W; Manufacturer: ROHM; Manufacturer P/N: MCR03EZPFX4991; Part Number: VISHAY CRCW0603649RFKEA; Vendor: Digikey; Vendor P/N: RHM4.99KHCT-ND; Volts/Amps/Watts: 0.1w
R105 = RES_0: RES, 0603 10K OHMS 5% 1/10W; Part Number: VISHAY CRCW060310K0JNEA
R106 = RESISTOR_1: RES, 0603 OPTION; Part Number: OPTION
R107 = RESISTOR_1: RES, 0603 34.8K OHM 1% 1/10W; Part Number: VISHAY CRCW060334K8FKEA; Tolerance: 1%
U4 = LT1761ES5-3_0.3: IC, REGULATOR; Part Number: LINEAR TECH. LT1761ES5-SD
U5 = LT1129CS8-3_1.3: IC, LTC6992; Part Number: LINEAR TECH. LTC6992IS6-1
U6 = LT1129CS8-3_2.3: IC, SINGLE OP AMP; Part Number: LINEAR TECH. LT1803IS5
D5 D6 D8 D9 = DIODE-LED_2: LED, 0603 GREEN; Manufacturer: PANASONIC; Manufacturer P/N: LN1371SGTRP; Part Number: WURTH ELEKTRONIK 150060GS75000
D7 = DIODE-LED_2: LED, 0603 RED; Label: GREEN; Manufacturer: PANASONIC; Part Number: WURTH ELEKTRONIK 150060SS75000
D10 D11 = DIODE_SCHOTTKY_9: DIODE, SCHOTTKY 30V, 100mA OPTION; Part Number: CENTRAL SEMI CMDSH-3-TR OPTION
D12 = DIODE_SCHOTTKY_0: DIODE, ULTRA LOW  SCHOTTKY RECTIEIER; Part Number: NXP SEMI. PMEG2005AEL,315
J7 = HD2X6-079-PMBUS_2: HEADER, 12PIN 2mm STR DL; Label: DC1427A HEADER; Manufacturer: MOLEX; Manufacturer P/N: 87831-1220; Part Number: FCI 98414-G06-12ULF; Type: header 12POS 2MM VERT; Vendor: Digikey; Vendor P/N: WM18561-ND
J8 = PMBUS_CONNECTOR20_3: CONN, SOCKET 14PIN  DUAL ROW R/A; Component: con; Manufacturer: Mill Max; Manufacturer P/N: 803-93-020-20-001; Part Number: SULLINSINC. NPPN072FJFN-RC; Part Type: HDR2X10RA; Type: conn  RA 20 dual row; Vendor: LTC; Vendor P/N: 803-93-020-20-001
J9 = PMBUS_HEADER20_3: HEADER, 14PIN DUAL ROW R/A; Component: con; Manufacturer: Mill Max; Manufacturer P/N: 802-40-020-20-0001; Part Number: MOLEX 87760-1416; Part Type: HDR_2X10_RA_REV; Type: header RA 20 dual row; Vendor: LTC; Vendor P/N: 802-40-020-20-001
J16 = HD2X6-079-PMBUS_4: HEADER, 4PIN 2mm STR DL; Manufacturer: Hirose; Part Number: HIROSE DF3A-4P-2DSA; Type: header 4POS 2MM VERT
Q19 Q20 = P-MOSFET: XSTR, N-CHANNEL DMOS FET; Part Number: DIODES INC. DMP3130L-7
Q21 Q26 = TRANSISTOR_0: XSTR, N-CHANNEL DMOS FET; Part Number: DIODES INC 2N7002A-7
Q22 Q25 = TRANSISTOR_1: XSTR, N-CHANNEL DMOS FET; Part Number: DIODES INC 2N7002A-7
R61 R62 R64 R67 R68 R75 R126 R142 R146 = RES0603_0: RES, 0603 OPTION; Label: OPT 0; Manufacturer: Rohm; Manufacturer P/N: RHM0.0GCT-ND; Part Number: OPTION; Tolerance: 5%; Vendor: Digikey; Vendor P/N: RHM0.0GCT-ND; Volts/Amps/Watts: 0.1W
R63 R65 = RES0603_0: RES, 0603 0 OHMS JUMPER; Label: OPT 0; Manufacturer: Rohm; Manufacturer P/N: RHM0.0GCT-ND; Part Number: VISHAY CRCW06030000Z0EA; Tolerance: 5%; Vendor: Digikey; Vendor P/N: RHM0.0GCT-ND; Volts/Amps/Watts: 0.1W
R69 R70 = RES0603_1: RES, 0603 10 OHMS 5% 1/10W; Manufacturer: Rohm; Manufacturer P/N: RHM0.0GCT-ND; Part Number: VISHAY CRCW060310R0JNEA; Tolerance: 5%; Vendor: Digikey; Vendor P/N: RHM0.0GCT-ND; Volts/Amps/Watts: 0.1W
R72 R73 = RES0603_0: RES, 0603 4.99K OHMS 1% 1/10W; Manufacturer: ROHM; Manufacturer P/N: MCR03EZPFX4991; Part Number: VISHAY CRCW06034K99FKEA; Vendor: Digikey; Vendor P/N: RHM4.99KHCT-ND; Volts/Amps/Watts: 0.1w
R74 R139 = RES0603_3: RES, 0603 OPTION; Label: OPT 0; Manufacturer: Rohm; Manufacturer P/N: RHM0.0GCT-ND; Part Number: OPTION; Tolerance: 5%; Vendor: Digikey; Vendor P/N: RHM0.0GCT-ND; Volts/Amps/Watts: 0.1W
R77 = RES0603_11: RES, 0603 10K OHMS 5% 1/10W; Part Number: VISHAY CRCW060310K0JNEA
R78 = RES0603_11: RES, 0603 15.8K OHMS 1% 1/10W; Part Number: VISHAY CRCW060315K8FKEA
R79 R80 R125 R130 = RES0603_0: RES, 0603 200 OHMS 5% 1/10W; Label: OPT 0; Manufacturer: Rohm; Manufacturer P/N: RHM0.0GCT-ND; Part Number: VISHAY CRCW0603200RJNEA; Tolerance: 5%; Vendor: Digikey; Vendor P/N: RHM0.0GCT-ND; Volts/Amps/Watts: 0.1W
R81 = RES0603_0: RES, 0603 127 OHMS 1% 1/10W; Label: OPT 0; Manufacturer: Rohm; Manufacturer P/N: RHM0.0GCT-ND; Part Number: VISHAY CRCW0603127RFKEA; Tolerance: 5%; Vendor: Digikey; Vendor P/N: RHM0.0GCT-ND; Volts/Amps/Watts: 0.1W
SW1 SW2 = JP3X1_079_NO_12_3: SWITCH, SUBMINATURE SLIDE; Part Number: C&K JS202011CQN
U3 = 24LC025-I_SN: IC, 24LC05-I/ST; Part Number: MICROCHIP 24LC025-I/ST
LRE1-LRE6 = Lug_Ring: LUG RING, #10; Part Number: KEYSTONE 8205
MH1-MH4 = CON1: STANDOFF, SNAP ON; Part Number: KEYSTONE 8834
NE1-NE6 NE11-NE16 = NUT: NUT, BRASS 10-32; Part Number: ANY #10-32
WE1-WE6 = Washer: WASHER, #10 TIN PLATED BRASS; Part Number: ANY #10 EXT BZ TN

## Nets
3V3: J7.5(LGKPWR) Q19.3(D) Q20.2(S) R79.1 R80.1 R125.1 R130.1 R146.1
+5.5V: C31.1 C41.2 R91.2 R94.1 R106.1 R107.2 U4.5(OUT)
GND_POWER: C2.2 C3.1 C4.1 C6.1 C26.2 C27.2 C28.2 C30.2 C31.2 C32.2 C34.2 C35.2 C39.2 C41.1 C42.1 CIN1.2 CIN2.2 CIN3.2 CIN4.2 COUT1.2 COUT2.2 COUT3.2 COUT4.2 COUT5.2 COUT6.2 COUT7.2 COUT8.2 COUT17.2 COUT18.2 COUT19.2 COUT20.2 COUT21.1 COUT22.2 COUT23.2 COUT24.2 COUT25.2 COUT26.1 E2.1(A) E8.1(A) E21.1(A) J2.1(TP) J4.1(TP) J6.1(TP) J7.3(GND) J7.10(GND) J8.11(GND) J8.12(GND) J9.11(GND) J9.12(GND) J10.2 J10.3(GND_POWER) J10.4(GND_POWER) J10.5(GND_POWER) J11.2 J11.3(GND_POWER) J11.4(GND_POWER) J11.5(GND_POWER) J12.2 J12.3(GND_POWER) J12.4(GND_POWER) J12.5(GND_POWER) J16.2(GND) JP4.3 Q3.1 Q3.2 Q3.3 Q4.1 Q4.2 Q4.3 Q8.1 Q8.2 Q8.3 Q9.1 Q9.2 Q9.3 Q21.2(S) Q22.2(S) Q25.2(S) Q26.2(S) R16.1 R21.1 R78.2 R81.2 R85.1 R86.1 R96.1 R97.2 R98.1 R101.1 R102.1 R103.1(A) R103.2(WIPER) R104.2 R105.1 SW1.3 SW2.3 U1.41(PGND) U1.49(GND) U3.1(A0) U3.2(A1) U3.3(A2) U3.4(VSS) U3.7(WP) U4.2(GND) U5.2(GND) U6.2(V-)
GND_SIGNAL: C1.1 C7.1 C10.1 C11.1 C12.1 C13.1 C14.2 C17.2 E31.1(A) JP1.3 Q7.1(B) Q7.3(C) Q10.1(B) Q10.3(C) R23.2 R26.2 R28.2 R32.2 R36.2 R38.2
VDD25: C7.2 E12.1(A) R22.1 R25.1 R27.1 R31.1 R35.1 R37.1 U1.25(VDD25)
VDD33: C1.2 D12.1(CATHODE) E11.1(A) Q19.2(S) R6.2 R7.2 R8.2 R9.2 R10.2 R11.1 R12.2 R13.1 R29.2 R30.2 R33.2 R34.2 U1.28(VDD33)
VIN: C2.1 C30.1 C32.1 E1.1(A) J1.1(TP) R1.1 R2.1 R4.2 R77.1 R87.2 R139.1 R147.1 U4.1(IN)
VIN1: CIN1.1 CIN2.1 CIN3.1 CIN4.1 Q1.5 Q1.6(VIN1) Q1.7(VIN1) Q1.8(VIN1) Q2.5 Q2.6(VIN1) Q2.7(VIN1) Q2.8(VIN1) Q5.5 Q5.6(VIN1) Q5.7(VIN1) Q5.8(VIN1) Q6.5 Q6.6(VIN1) Q6.7(VIN1) Q6.8(VIN1) R1.2 R3.2
ALERTB: E22.1(A) J7.6(ALERTB) J8.3(ALERTB) J9.3(ALERTB) Q20.1(G) R10.1 U1.14(ALERTB)
ASEL0: R22.2 R23.1 U1.19(ASEL0)
ASEL1: R25.2 R26.1 U1.20(ASEL1)
AUX3V4: D12.2(ANODE) J16.4(AUX3V4)
AUXVCC: C26.1 E20.1(A) J7.1(AUXP) J8.8(AUXP) J9.8(AUXP) R72.1 R73.1 U3.8(VCC)
BG0: Q3.4 Q4.4 U1.42(BG0)
BG1: Q8.4 Q9.4 U1.37(BG1)
BST0: R15.1 U1.43(BOOST0)
EESCL: J7.11(AUXSCL) R72.2 U3.6(SCL)
EESDA: J7.12(AUXSDA) R73.2 U3.5(SDA)
EXTVCC: C6.2 E9.1(A) R106.2 U1.40(EXTVCC)
FAULT0B: D11.2(ANODE) E28.1(A) Q21.1(G) R29.1 R45.1 R63.2 R64.2 U1.15(FAULT0B)
FAULT1B: D10.2(ANODE) E27.1(A) Q22.1(G) R30.1 R45.2 R61.2 R62.2 U1.16(FAULT1B)
FREQ_CFG: R35.2 R36.1 U1.23(FREQ_CFG)
INTVCC: C4.2 D1.2(ANODE) D2.2(ANODE) E10.1(A) R147.2 U1.38(INTVCC)
ITH0: C10.2 R39.1 U1.6(ITH0)
ITH1: C12.2 R39.2 U1.29(ITH1)
PGOOD0: E13.1(A) Q26.1(G) R34.1 R46.1 U1.48(PGOOD0)
PGOOD1: E14.1(A) Q25.1(G) R33.1 R46.2 U1.33(PGOOD1)
PHASE_CFG: R37.2 R38.1 U1.24(PHASE_CFG)
RUN0: D11.1(CATHODE) E29.1(A) R8.1 R42.1 R62.1 R65.2 R70.2 R142.2 SW2.1 SW2.2 U1.17(RUN0)
RUN1: D10.1(CATHODE) E30.1(A) R7.1 R42.2 R64.1 R68.2 R69.2 R126.2 SW1.1 SW1.2 U1.18(RUN1)
SCL: E24.1(A) J7.4(SCL) J8.6(SCL) J9.6(SCL) J16.3(SCL) R12.1 U1.12(SCL)
SDA: E23.1(A) J7.2(SDA) J8.4(SDA) J9.4(SDA) J16.1(SDA) R11.2 U1.13(SDA)
SHARE_CLK: E25.1(A) R9.1 R66.1 U1.27(SHARE_CLK)
SW0: C8.1 L1.1 Q1.1 Q1.2 Q1.3 Q2.1 Q2.2 Q2.3 Q3.5 Q3.6(SW0) Q3.7(SW0) Q3.8(SW0) Q4.5 Q4.6(SW0) Q4.7(SW0) Q4.8(SW0) R14.1 U1.45(SW0)
SW1: C15.1 L2.1 Q5.1 Q5.2 Q5.3 Q6.1 Q6.2 Q6.3 Q8.5 Q8.6(SW1) Q8.7(SW1) Q8.8(SW1) Q9.5 Q9.6(SW1) Q9.7(SW1) Q9.8(SW1) R20.1 U1.34(SW1)
SYNC: E26.1(A) R13.2 R67.1 U1.11(SYNC)
TG0: Q1.4 Q2.4 U1.44(TG0)
TG1: Q5.4 Q6.4 U1.35(TG1)
TSNS0: C14.1 Q7.2(E) U1.10(TSNS0)
TSNS1: C17.1 Q10.2(E) U1.9(TSNS1)
VOUT0: COUT1.1 COUT2.1 COUT3.1 COUT4.1 COUT17.1 COUT18.1 COUT19.1 COUT20.1 COUT21.2 J3.1(TP) J10.1 L1.2 R5.2 R41.2 R44.2 R47.2 R48.2 R85.2 R88.1 R113.1
VOUT0_CFG: R27.2 R28.1 U1.21(VOUT0_CFG)
VOUT1: COUT5.1 COUT6.1 COUT7.1 COUT8.1 COUT22.1 COUT23.1 COUT24.1 COUT25.1 COUT26.2 J5.1(TP) J11.1 L2.2 R18.2 R41.1 R44.1 R47.1 R48.1 R86.2 R90.1 R114.1
VOUT1_CFG: R31.2 R32.1 U1.22(VOUT1_CFG)
VSENSE0+: E3.1(A) R5.1 R40.1 U1.1(VSENSE0+)
VSENSE0-: E4.1(A) R16.2 R43.1 U1.2(VSENSE0-)
VSENSE1+: E5.1(A) R18.1 R40.2 U1.32(VSENSE1+)
VSENSE1-: E6.1(A) R21.2 R43.2 U1.31(VSENSE1-)
WP1: JP1.2 R6.1 U1.26(WP)
N19055332: C3.2 R2.2 U1.39(VIN)
N19064724: C5.1 R3.1 U1.47(IIN-)
N19065153: C5.2 R4.1 U1.46(IIN+)
N19157069: C11.2 U1.5(ITH_R0)
N19167019: C13.2 U1.30(ITH_R1)
N19267856: C9.1 R14.2 R17.1 U1.7(ISENSE0+)
N19268092: C9.2 R17.2 R113.2 U1.8(ISENSE0-)
N19342055: C8.2 D1.1(CATHODE) R15.2
N19478637: C16.1 R20.2 R24.1 U1.3(ISENSE1+)
N19478647: C16.2 R24.2 R114.2 U1.4(ISENSE1-)
N19478879: C15.2 D2.1(CATHODE) R19.2
N20479472: C40.2 R92.1 U6.1(VOUT)
N20479484: R95.1 R99.1 U6.3(+IN)
N20479490: C39.1 R95.2 U5.6(OUT) U6.5(V+)
N20479492: C42.2 J12.1 Q23.3 Q24.3 R100.2 R101.2 R102.2
N20479532: C34.1 C35.1 Q23.2 Q24.2 R88.2 R90.2
N20479647: JP5.2 JP5.3 Q23.1 Q24.1 R89.2 R98.2
N20479673: JP5.1 R92.2
N20479683: E7.1(A) R89.1
N20479716: R94.2 R97.1 U5.4(DIV)
N20479804: R91.1 U5.5(V+)
N20479929: R93.1 R96.2 U5.1(MOD)
N20479960: C40.1 R100.1 U6.4(-IN)
N20480136: R99.2 R103.3(B) R104.1
N20480171: R93.2 U5.3(SET)
N20702664: JP4.1 R87.1
N20702670: JP4.2 U4.3(\\~{SHDN})
N20702697: R105.2 R107.1 U4.4(ADJ)
N21338054: R19.1 U1.36(BOOST1)
N21614108: D9.2(A) R130.2
N21614117: D9.1(K) Q26.3(D)
N21614140: D8.1(K) Q25.3(D)
N21614229: J8.1(FAULTB) J9.1(FAULTB) R61.1 R63.1 R126.1 R142.1
N21614290: J8.13(12V) J8.14(12V) J9.13(12V) J9.14(12V) R139.2
N21614303: J8.9(UNUSED) J9.9(UNUSED) R67.2
N21614325: J8.7(RESETB) J9.7(RESETB)
N21614327: J8.5(SHARE_CLK) J9.5(SHARE_CLK) R66.2
N21614335: J8.10(UNUSED) J9.10(UNUSED) R146.2
N21614341: J8.2(CTRL) J9.2(CTRL) R65.1 R68.1 R74.2 R75.2
N21614437: C27.1 R69.1
N21614583: C28.1 R70.1
N21614664: D8.2(A) R125.2
N21614737: J7.8(OUTEN_0) R74.1
N21614739: J7.9(OUTEN_1) R75.1
N21614792: Q19.1(G) R77.2 R78.1
N21615208: D5.2(A) R79.2
N21615232: D6.2(A) R80.2
N21615236: D5.1(K) Q21.3(D)
N21615254: D6.1(K) Q22.3(D)
N21615317: D7.2(A) Q20.3(D)
N21615336: D7.1(K) R81.1

Not connected (* = marked no-connect by the designer): J7 7(GPIO_1); JP1 1; MH1 1; MH2 1; MH3 1; MH4 1; SW1 4 5 6; SW2 4 5 6

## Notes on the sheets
sheet 1
- HARDWARE
- STANDOFFS
sheet 2
- OPTIONAL 5.5V BIAS
- 2010
- OPT
- 2010
- OPT
- BIAS
- ON
- BLEEDER LOADS
- OFF
- DYNAMIC LOAD TEST CIRCUIT, FOR DEMO BOARD ONLY
- VOUT0
- VOUT1
- PULSE
- INT
- EXT
- 70Hz, 3% Duty Cycle
- IOUT STEP
- 1%
- 1%
sheet 3
- 4.5V - 14V
- 744301025
- 1.0V AT 30A
- WP
- ON
- OFF
- 744301025
- 1.0V AT 30A
- OPTION FOR TWO-PHASE CONFIGURATION CONNECTION
- NOTE:
  T1 - T8 ARE EXPOSED PCB VIAS
  FOR USE AS TEST POINTS
- NOTE:
  VOUT0 AND VOUT1 DEFAULT OUTPUT = 1.8V
- LTC3880EUJ - CURRENT MODE DUAL PHASE / DUAL CHANNEL
  STEP-DOWN CONTROLLER WITH I2C / PMBus INTERFACE
- MAKE ALL SENSE CONNECTIONS TO L1/L2
  AND R10/R16 DIFFERENTIAL AND KELVIN
sheet 4
- ALL PARTS ON THIS PAGE ARE FOR DEMO BOARD ONLY, NOT NEEDED IN CUSTOMER DESIGN
- TO DC2086A
- TO DC1613A
- RUN1
- RUN0
- ON
- ON
- OFF
- OFF
- 1206
- PGOOD0
- GPIO0
- GPIO1
- PGOOD1
- ALERTB
